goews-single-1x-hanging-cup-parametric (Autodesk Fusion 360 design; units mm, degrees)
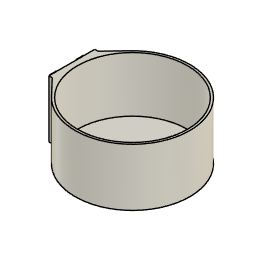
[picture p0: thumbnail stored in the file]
parameter "CupInner_Diam" = 100
parameter "CupWall" = 2
parameter "Height" = 50
parameter "bottomThickness" = 2
base_feature "Base Feature" bodies "Cup", "Single Plate Blank"
delete_face "DeleteFace1"
sketch "Sketch1" plane through (99.15, 0, 0) normal (1, 0, 0) x axis (0, 1, 0)
  line L1 (20.8, -177.7602) -> (20.8, -206.2982)
  line L2 (6.9847, -177.7602) -> (20.8, -177.7602)
  line L3 (-20.8, -177.7602) -> (-6.9847, -177.7602)
  line L4 (-20.8, -206.2982) -> (-20.8, -177.7602)
  line L5 (20.8, -206.2982) -> (-20.8, -206.2982)
  line L6 (6.9847, -177.7602) -> (-6.9847, -177.7602)
  line L7 (0, -184.2983) -> (0, -177.7602)
  arc A1 centre (0, -177.2983) radius 7 clockwise from (6.9847, -177.7602) to (-6.9847, -177.7602)
  point P5 (-6.9847, -177.7602)
  point P9 (-6.9847, -177.7602)
  point P4 (6.9847, -177.7602)
  point P10 (6.9847, -177.7602)
  point P11 (0, -177.7602)
  point P12 (0, -184.2983)
  coincident P5 P9
  coincident P4 P10
  midpoint L6 P11
  midpoint A1 P12
  dimension "d53" distance P11 P12 = 6.5381
extrude "Extrude5" add sketch "Sketch1" profile of A1 L6 L7 against normal blind 3
move_face "MoveFace2"
sketch "Sketch2" plane through (0, 0, -184.2982) normal (0, 0, 1) x axis (-1, 0, 0)
  line L1 (-99.15, -20.8) -> (-99.15, 20.8)
  line L2 (-96.15, -20.8) -> (-99.15, -20.8)
  line L3 (-96.15, 20.8) -> (-96.15, -20.8)
  line L4 (-99.15, 20.8) -> (-96.15, 20.8)
  line L5 (-99.15, 0) -> (-99.15, 20.8)
  line L6 (-196.15, 0) -> (-96.15, 0)
  line L7 (-99.15, 0) -> (-99.15, -20.8)
  line L8 (-99.15, 20.8) -> (-99.15, -20.8)
  line L9 (-99.15, 20.8) -> (-99.15, -20.8)
  line L10 (-114.3804, 36.7696) -> (-151.15, 0)
  line L11 (-99.15, 0) -> (-151.15, 0)
  line L12 (-114.3804, -36.7696) -> (-151.15, 0)
  line L13 (-114.3804, -36.7696) -> (-99.15, -20.8)
  line L14 (-114.3804, 36.7696) -> (-99.15, 20.8)
  circle C1 centre (-151.15, 0) radius 52
  circle C2 centre (-151.15, 0) radius 50
  point P2 (-99.15, 20.8)
  point P8 (-99.15, 20.8)
  point P9 (-99.15, 0)
  point P10 (-96.15, 0)
  point P6 (-151.15, 0)
  point P12 (-99.15, 0)
  point P13 (-99.15, -20.8)
  point P15 (-99.15, -20.8)
  point P17 (-99.15, -20.8)
  point P19 (-99.15, 20.8)
  point P16 (-99.15, 0)
  point P20 (-151.15, 0)
  point P21 (-114.3804, 36.7696)
  point P23 (-151.15, 0)
  point P24 (-114.3804, -36.7696)
  point P25 (-99.15, 20.8)
  point P11 (-196.15, 0)
  coincident P2 P8
  coincident C1 P9
  tangent C1 L5
  midpoint L3 P10
  perpendicular L3 L6
  coincident P6 L6
  coincident C1 P12
  coincident P13 P15
  coincident P13 P17
  tangent C1 L7
  coincident P2 P19
  coincident C1 P16
  horizontal L11
  coincident P6 P20
  coincident C1 P21
  coincident P6 P23
  coincident C1 P24
  coincident P2 P25
  dimension "d40" diameter C1 = 104 (= "CupInner_Diam + ( CupWall * 2 )")
  dimension "d47" distance P10 P11 = 100
  dimension "d56" angle L10 L11 = 45 (= "Angular Dimension-2")
  dimension "d57" angle L10 L12 = 90 (= "Angular Dimension-3")
extrude "Extrude2" add sketch "Sketch2" profile of L1 C1 C2 L5 L7 L8 L9 L13 L14
sketch "Sketch4" plane through (0, 0, -236.2982) normal (0, 0, -1) x axis (1, 0, 0)
  line L1 (96.15, 20.8) -> (99.15, 20.8)
  line L2 (96.15, -20.8) -> (96.15, 20.8)
  line L3 (99.15, -20.8) -> (96.15, -20.8)
  line L4 (112.6806, -34.9872) -> (99.15, -20.8)
  line L5 (99.15, 20.8) -> (112.6806, 34.9872)
  circle C1 centre (151.15, 0) radius 50
  arc A1 centre (151.15, 0) radius 52 clockwise from (112.6806, 34.9872) to (112.6806, -34.9872)
extrude "Extrude7" add sketch "Sketch4" profile of C1
named bodies: "Cup", "Single Plate Blank"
